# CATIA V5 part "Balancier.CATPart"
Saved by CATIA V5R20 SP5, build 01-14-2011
Part number: Balancier
Bounding box of the stored display mesh (mm): x -40 to 40, y -40 to 250, z -20 to 50
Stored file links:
  F:\IAO_bmadec\bmadecf\Balancier.CATPart
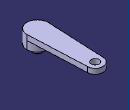
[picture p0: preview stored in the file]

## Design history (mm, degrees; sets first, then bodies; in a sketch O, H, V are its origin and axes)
Body1 (main body)
  Sketch1 on xy-plane, origin (0, 0, 0), H (1, 0, 0), V (0, 1, 0)
    circle A1 centre (0, 0) radius 40
    radius A1 = 40
  Pad1: profile Sketch1, direction (0, 0, 1), length 30
  Sketch2 on start face of Pad1, origin (0, 0, 0), H (1, 0, 0), V (0, -1, 0)
    circle A1 centre (0, 0) radius 20
    radius A1 = 20
  Pad2: profile Sketch2, direction (0, 0, -1), length 20
  Chamfer1: length 1, angle 45, on edge [face of Pad2 from Sketch2.A1 | end face of Pad2]
  Sketch3 on end face of Pad1, origin (0, 0, 30), H (1, 0, 0), V (0, 1, 0)
    arc A1 centre (0, 0) radius 40 from (-40, 0) to (40, 0) ccw
    point P1 (-40, 0)
    point P2 (40, 0)
    arc A2 centre (0, 220) radius 30 from (30, 220) to (-30, 220) ccw
    point P3 (0, 220)
    point P4 (30, 220)
    point P5 (-30, 220)
    line L1 (-40, 0) -> (-30, 220)
    line L2 (40, 0) -> (30, 220)
    distance P5 P3 V = 0
    distance P4 P3 V = 0
    radius A2 = 30
    radius A1 = 40
    distance P3 O = 220
    coincidence: P1 H, P2 H, P3 V
  Pad3: profile Sketch3, direction (0, 0, 1), length 20
  Sketch4 on end face of Pad3, origin (6.6993, 216.1594, 50), H (1, 0, 0), V (0, 1, 0)
    point P1 (-6.6993, 3.8406)
    reference projected arc E1 centre (-6.6993, 3.8406) radius 30 from (23.3007, 3.8406) to (-36.6993, 3.8406) ccw from edge [face of Pad3 from Sketch3.A2 | end face of Pad3]
    concentricity: P1 E1
  Hole1: placed by Sketch4, at (0, 220, 50) direction (0, 0, -1), diameter 30, through (limit type 6)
